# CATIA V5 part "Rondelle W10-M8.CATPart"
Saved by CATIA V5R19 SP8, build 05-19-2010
Part number: Rondelle W10-M8
Nomenclature: 35
Source: Unknown
Description: PART-ronw8a2-DESC
Bounding box of the stored display mesh (mm): x 0 to 2, y -7.397 to 7.391, z -7.4 to 7.4
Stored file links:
  C:\Users\rphgr\Desktop\0_Tapis_TC520B_vitesse\Rondelle W10-M8.CATPart
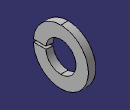
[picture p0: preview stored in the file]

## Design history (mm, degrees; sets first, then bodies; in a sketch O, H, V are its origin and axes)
AxisSystem1: origin (0, 0, 0), X (1, 0, 0), Y (0, 1, 0), Z (0, 0, 1)
Body1 "ronw8a2" (main body)
  Solid1: solid without history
